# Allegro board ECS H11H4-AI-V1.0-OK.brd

Outline 200 x 210 mm; copper layers: TOP, PWR, GND, BOTTOM. Coordinates in mm from the lower left corner of the outline.
Outline path: 0,206.95 0,3.05 ; 0,206.95 arc(0.89,209.11) 3.05,210 ; 0,206.95 0,3.05 ; 0,3.05 arc(0.89,0.89) 3.05,0 ; 3.05,210 196.95,210 ; 3.05,210 196.95,210 ; 196.95,210 arc(199.11,209.11) 200,206.95 ; 3.05,0 196.95,0 ; 3.05,0 196.95,0 ; 196.95,0 arc(199.11,0.89) 200,3.05 ; 200,206.95 200,3.05 ; 200,206.95 200,3.05

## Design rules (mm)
net group DIFFPAIR351: nets CPU_BCLK_N CPU_BCLK_P
net group DIFFPAIR353: nets CPU_24MCLK_N CPU_24MCLK_P
net group DIFFPAIR381: nets USB_H1 USB_L1
net group DIFFPAIR382: nets USB_H2 USB_L2
net group DIFFPAIR422: nets USB+7 USB-7
net group DIFFPAIR436: nets VCORE_GSENS VCORE_SENS
net group DIFFPAIR439: nets VCORE_GT_GSENS VCORE_GT_SENS
net group DIFFPAIR448: nets USB3_TX_N2_C USB3_TX_P2_C
net group DIFFPAIR455: nets MXDIN_0 MXDIP_0
net group DIFFPAIR456: nets MXDIN_1 MXDIP_1
net group DIFFPAIR457: nets MXDIN_2 MXDIP_2
net group DIFFPAIR458: nets MXDIN_3 MXDIP_3
net group DIFFPAIR459: nets HSIN HSIP
net group DIFFPAIR460: nets GLAN_TX_N7 GLAN_TX_P7
net group DIFFPAIR461: nets HSON HSOP
net group DIFFPAIR462: nets GLAN_RX_N7 GLAN_RX_P7
net group DIFFPAIR463: nets DP_TX_N1 DP_TX_P1
net group DIFFPAIR464: nets DP_TX_N0 DP_TX_P0
net group DIFFPAIR465: nets DP_AUX_N DP_AUX_P
net group DIFFPAIR467: nets SATA3T_N0 SATA3T_P0
net group DIFFPAIR468: nets SATA3R_N0 SATA3R_P0
net group DIFFPAIR469: nets SATA3R_N1 SATA3R_P1
net group DIFFPAIR470: nets SATA3_TX_N1 SATA3_TX_P1
net group DIFFPAIR471: nets SATA3T_N1 SATA3T_P1
net group DIFFPAIR472: nets M_DQS_A_N8 M_DQS_A_P8
net group DIFFPAIR485: nets HDMI_CLK_N3 HDMI_CLK_P3
net group DIFFPAIR486: nets DDI3_TX_N3 DDI3_TX_P3
net group DIFFPAIR487: nets DDI3_TX_N2 DDI3_TX_P2
net group DIFFPAIR488: nets HDMI_TX_N0 HDMI_TX_P0
net group DIFFPAIR489: nets HDMI_TX_N1 HDMI_TX_P1
net group DIFFPAIR490: nets DDI3_TX_N1 DDI3_TX_P1
net group DIFFPAIR491: nets HDMI_TX_N2 HDMI_TX_P2
net group DIFFPAIR492: nets DDI3_TX_N0 DDI3_TX_P0
net group DIFFPAIR496: nets M_DQS_B_N8 M_DQS_B_P8
net group DIFFPAIR497: nets VR_CSN2 VR_CSP2
net group DIFFPAIR498: nets VR_CSN1 VR_CSP1
net group DIFFPAIR499: nets VR_CSN3 VR_CSP3
net group DIFFPAIR500: nets VR_CSN1A VR_CSP1A
net group DIFFPAIR501: nets VR_CSN2A VR_CSP2A
net group GLAN: nets GLAN_CLKN GLAN_CLKP
net group PCH-CLK: nets PEX16_100M_N PEX16_100M_P
net group VRD: nets VRD_THERMDA VRD_THERMDC
net group DDI1: nets DDI1_AUX_N DDI1_AUX_P DDI1_TX_N0 DDI1_TX_N1 DDI1_TX_P0 DDI1_TX_P1
net group DDR_DQS_A: nets M_DQS_A_N0 M_DQS_A_N1 M_DQS_A_N2 M_DQS_A_N3 M_DQS_A_N4 M_DQS_A_N5 M_DQS_A_N6 M_DQS_A_N7 M_DQS_A_P0 M_DQS_A_P1 M_DQS_A_P2 M_DQS_A_P3 M_DQS_A_P4 M_DQS_A_P5 M_DQS_A_P6 M_DQS_A_P7
net group DDR_DQS_B: nets M_DQS_B_N0 M_DQS_B_N1 M_DQS_B_N2 M_DQS_B_N3 M_DQS_B_N4 M_DQS_B_N5 M_DQS_B_N6 M_DQS_B_N7 M_DQS_B_P0 M_DQS_B_P1 M_DQS_B_P2 M_DQS_B_P3 M_DQS_B_P4 M_DQS_B_P5 M_DQS_B_P6 M_DQS_B_P7
net group DDRCLK-A: nets M_CLK_A_N0 M_CLK_A_N1 M_CLK_A_P0 M_CLK_A_P1
net group DDRCLK-B: nets M_CLK_B_N0 M_CLK_B_N1 M_CLK_B_P0 M_CLK_B_P1
net group DDRCMD-A: nets M_ACT_A_L M_BA_A0 M_BA_A1 M_BG_A0 M_BG_A1 M_MA_A0 M_MA_A1 M_MA_A2 M_MA_A3 M_MA_A4 M_MA_A5 M_MA_A6 M_MA_A7 M_MA_A8 M_MA_A9 M_MA_A10 M_MA_A11 M_MA_A12 M_MA_A13 M_MA_A14 M_MA_A15 M_MA_A16 M_PARITY_A
net group DDRCMD-B: nets M_ACT_B_L M_BA_B0 M_BA_B1 M_BG_B0 M_BG_B1 M_MA_B0 M_MA_B1 M_MA_B2 M_MA_B3 M_MA_B4 M_MA_B5 M_MA_B6 M_MA_B7 M_MA_B8 M_MA_B9 M_MA_B10 M_MA_B11 M_MA_B12 M_MA_B13 M_MA_B14 M_MA_B15 M_MA_B16 M_PARITY_B
net group DDRCTRL-A: nets M_CKE_A0 M_CKE_A1 M_CS_A_L0 M_CS_A_L1 M_ODT_A0 M_ODT_A1
net group DDRCTRL-B: nets M_CKE_B0 M_CKE_B1 M_CS_B_L0 M_CS_B_L1 M_ODT_B0 M_ODT_B1
net group DIFF-CLK: nets CPU_PCIBCLK_N
net group DIFFPAIR352: nets CPU_PCIBCLK_P
net group DMI: nets DMI_RX_N0 DMI_RX_N1 DMI_RX_N2 DMI_RX_N3 DMI_RX_P0 DMI_RX_P1 DMI_RX_P2 DMI_RX_P3 DMI_TX_N0 DMI_TX_N1 DMI_TX_N2 DMI_TX_N3 DMI_TX_P0 DMI_TX_P1 DMI_TX_P2 DMI_TX_P3
net group HDMI: nets HDMI_CLK_N3_R HDMI_CLK_P3_R HDMI_TX_N0_R HDMI_TX_N1_R HDMI_TX_N2_R HDMI_TX_P0_R HDMI_TX_P1_R HDMI_TX_P2_R
net group M_DATA_A: nets M_DATA_A0 M_DATA_A1 M_DATA_A2 M_DATA_A3 M_DATA_A4 M_DATA_A5 M_DATA_A6 M_DATA_A7 M_DATA_A8 M_DATA_A9 M_DATA_A10 M_DATA_A11 M_DATA_A12 M_DATA_A13 M_DATA_A14 M_DATA_A15 M_DATA_A16 M_DATA_A17 M_DATA_A18 M_DATA_A19 M_DATA_A20 M_DATA_A21 M_DATA_A22 M_DATA_A23 M_DATA_A24 M_DATA_A25 M_DATA_A26 M_DATA_A27 M_DATA_A28 M_DATA_A29 M_DATA_A30 M_DATA_A31 M_DATA_A32 M_DATA_A33 M_DATA_A34 M_DATA_A35 M_DATA_A36 M_DATA_A37 M_DATA_A38 M_DATA_A39 M_DATA_A40 M_DATA_A41 M_DATA_A42 M_DATA_A43 M_DATA_A44 M_DATA_A45 M_DATA_A46 M_DATA_A47 M_DATA_A48 M_DATA_A49 M_DATA_A50 M_DATA_A51 M_DATA_A52 M_DATA_A53 M_DATA_A54 M_DATA_A55 M_DATA_A56 M_DATA_A57 M_DATA_A58 M_DATA_A59 M_DATA_A60 M_DATA_A61 M_DATA_A62 M_DATA_A63 M_DATA_A_CB0 M_DATA_A_CB1 M_DATA_A_CB2 M_DATA_A_CB3 M_DATA_A_CB4 M_DATA_A_CB5 M_DATA_A_CB6 M_DATA_A_CB7
net group M_DATA_B: nets M_DATA_B0 M_DATA_B1 M_DATA_B2 M_DATA_B3 M_DATA_B4 M_DATA_B5 M_DATA_B6 M_DATA_B7 M_DATA_B8 M_DATA_B9 M_DATA_B10 M_DATA_B11 M_DATA_B12 M_DATA_B13 M_DATA_B14 M_DATA_B15 M_DATA_B16 M_DATA_B17 M_DATA_B18 M_DATA_B19 M_DATA_B20 M_DATA_B21 M_DATA_B22 M_DATA_B23 M_DATA_B24 M_DATA_B25 M_DATA_B26 M_DATA_B27 M_DATA_B28 M_DATA_B29 M_DATA_B30 M_DATA_B31 M_DATA_B32 M_DATA_B33 M_DATA_B34 M_DATA_B35 M_DATA_B36 M_DATA_B37 M_DATA_B38 M_DATA_B39 M_DATA_B40 M_DATA_B41 M_DATA_B42 M_DATA_B43 M_DATA_B44 M_DATA_B45 M_DATA_B46 M_DATA_B47 M_DATA_B48 M_DATA_B49 M_DATA_B50 M_DATA_B51 M_DATA_B52 M_DATA_B53 M_DATA_B54 M_DATA_B55 M_DATA_B56 M_DATA_B57 M_DATA_B58 M_DATA_B59 M_DATA_B60 M_DATA_B61 M_DATA_B62 M_DATA_B63 M_DATA_B_CB0 M_DATA_B_CB1 M_DATA_B_CB2 M_DATA_B_CB3 M_DATA_B_CB4 M_DATA_B_CB5 M_DATA_B_CB6 M_DATA_B_CB7
net group PCIE-16X: nets PEG_RX_N0 PEG_RX_N1 PEG_RX_N2 PEG_RX_N3 PEG_RX_N4 PEG_RX_N5 PEG_RX_N6 PEG_RX_N7 PEG_RX_N8 PEG_RX_N9 PEG_RX_N10 PEG_RX_N11 PEG_RX_N12 PEG_RX_N13 PEG_RX_N14 PEG_RX_N15 PEG_RX_P0 PEG_RX_P1 PEG_RX_P2 PEG_RX_P3 PEG_RX_P4 PEG_RX_P5 PEG_RX_P6 PEG_RX_P7 PEG_RX_P8 PEG_RX_P9 PEG_RX_P10 PEG_RX_P11 PEG_RX_P12 PEG_RX_P13 PEG_RX_P14 PEG_RX_P15 PEG_TX_C_N0 PEG_TX_C_N1 PEG_TX_C_N2 PEG_TX_C_N3 PEG_TX_C_N4 PEG_TX_C_N5 PEG_TX_C_N6 PEG_TX_C_N7 PEG_TX_C_N8 PEG_TX_C_N9 PEG_TX_C_N10 PEG_TX_C_N11 PEG_TX_C_N12 PEG_TX_C_N13 PEG_TX_C_N14 PEG_TX_C_N15 PEG_TX_C_P0 PEG_TX_C_P1 PEG_TX_C_P2 PEG_TX_C_P3 PEG_TX_C_P4 PEG_TX_C_P5 PEG_TX_C_P6 PEG_TX_C_P7 PEG_TX_C_P8 PEG_TX_C_P9 PEG_TX_C_P10 PEG_TX_C_P11 PEG_TX_C_P12 PEG_TX_C_P13 PEG_TX_C_P14 PEG_TX_C_P15 PEG_TX_N0 PEG_TX_N1 PEG_TX_N2 PEG_TX_N3 PEG_TX_N4 PEG_TX_N5 PEG_TX_N6 PEG_TX_N7 PEG_TX_N8 PEG_TX_N9 PEG_TX_N10 PEG_TX_N11 PEG_TX_N12 PEG_TX_N13 PEG_TX_N14 PEG_TX_N15 PEG_TX_P0 PEG_TX_P1 PEG_TX_P2 PEG_TX_P3 PEG_TX_P4 PEG_TX_P5 PEG_TX_P6 PEG_TX_P7 PEG_TX_P8 PEG_TX_P9 PEG_TX_P10 PEG_TX_P11 PEG_TX_P12 PEG_TX_P13 PEG_TX_P14 PEG_TX_P15
net group RGB: nets VGA_BLUE VGA_GREEN VGA_RED
net group SATA30: nets SATA3_RX_N0 SATA3_RX_N1 SATA3_RX_P0 SATA3_RX_P1 SATA3_TX_N0 SATA3_TX_P0
net group USB20: nets SMBDATA_STBY USB+5 USB+6 USB+8 USB-5 USB-6 USB-8 USB_N1 USB_N2 USB_N5 USB_N6 USB_N7 USB_N8 USB_P1 USB_P2 USB_P5 USB_P6 USB_P7 USB_P8
net group USB30: nets USB3_RX_N1 USB3_RX_N1_R USB3_RX_N2 USB3_RX_N2_R USB3_RX_N3 USB3_RX_N3_R USB3_RX_N4 USB3_RX_N4_R USB3_RX_P1 USB3_RX_P1_R USB3_RX_P2 USB3_RX_P2_R USB3_RX_P3 USB3_RX_P3_R USB3_RX_P4 USB3_RX_P4_R USB3_TX_N1 USB3_TX_N1_C USB3_TX_N1_R USB3_TX_N2 USB3_TX_N2_R USB3_TX_N3 USB3_TX_N3_C USB3_TX_N3_R USB3_TX_N4 USB3_TX_N4_C USB3_TX_N4_R USB3_TX_P1 USB3_TX_P1_C USB3_TX_P1_R USB3_TX_P2 USB3_TX_P2_R USB3_TX_P3 USB3_TX_P3_C USB3_TX_P3_R USB3_TX_P4 USB3_TX_P4_C USB3_TX_P4_R USB_N3 USB_N3_R USB_N4 USB_N4_R USB_P3 USB_P3_R USB_P4 USB_P4_R

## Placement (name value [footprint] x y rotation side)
ATX_12V  -  [ATX_PWR_4P_2]  190.73 163.65 180 top
ATX_POWER  -  [ATX_PWR_12P-RUIYE_2]  82.73 8.58 0 top
AUDIO  -  [AUDIO_JACK_13P-COLAY_2]  52.09 201.42 0 top
BAT1  +  [BATTERY_HOLDER_CR2032-LOTES]  35.22 131.27 180 top
BIOS_WP  -  [J3X1]  44.23 64.14 0 top
BZ  +  [BUZZER_1]  182.28 68.33 270 top
C1  -  [C0402_2]  179.24 204.16 180 top
C2  -  [C0402_2]  179.24 202.95 180 top
C3  -  [C0402_2]  166.15 202.57 270 top
C4  -  [C0402_2]  167.23 202.57 270 top
C5  -  [C0402_2]  103.1 202.44 0 top
C6  -  [C0402_2]  179.24 201.62 180 top
C7  -  [C0402_2]  179.24 200.28 180 top
C8  -  [C0402_2]  110.48 200.07 270 top
C9  -  [C0805_2]  112.7 199.76 180 top
C10  -  [C0603_2]  128.6 199.34 270 top
C11  -  [C0805_2]  103.16 199.14 270 top
C12  -  [C0402_2]  127.39 198.96 90 top
C13  -  [C0402_2]  179.24 198.95 180 top
C14  -  [C0402_2]  8.74 198.82 90 top
C15  -  [C0402_2]  134.02 197.55 0 top
C16  -  [C0402_2]  103.1 196.92 0 top
C17  -  [C0402_2]  118.21 196.86 270 top
C18  -  [C0402_2]  119.55 196.86 270 top
C19  -  [C0402_2]  121.13 196.86 270 top
C20  -  [C0402_2]  122.21 196.86 270 top
C21  -  [C0402_2]  123.29 196.86 270 top
C22  -  [C0402_2]  124.37 196.86 270 top
C23  -  [C0402_2]  125.45 196.86 270 top
C24  -  [C0402_2]  115.1 196.79 270 top
C25  -  [C0402_2]  116.62 196.79 270 top
C26  -  [C0402_2]  8.74 196.67 90 top
C27  -  [C0402_2]  134.02 196.47 0 top
C28  -  [C0402_2]  103.1 195.84 0 top
C29  -  [C0402_2]  134.02 195.4 0 top
C30  -  [C0402_2]  8.74 194.57 270 top
C31  -  [C0402_2]  134.02 194.32 0 top
C32  -  [C0402_2]  18.58 193.87 90 top
C33  -  [C0805_2]  17.06 193.81 90 top
C34  -  [C0805_2]  21.25 193.81 90 top
C35  -  [C0805_2]  23.22 193.81 90 top
C36  -  [C0805_2]  25.18 193.81 270 top
C37  -  [C0805_2]  27.15 193.81 270 top
C38  -  [C0402_2]  115.42 193.68 0 top
C39  -  [C0402_2]  117.83 193.68 0 top
C40  -  [C0402_2]  120.24 193.68 0 top
C41  -  [C0402_2]  134.02 193.24 0 top
C42  -  [C0402_2]  8.74 192.35 270 top
C43  -  [C0402_2]  134.02 192.16 0 top
C44  -  [C0402_2]  84.62 191.14 270 top
C45  -  [C0402_2]  134.02 191.08 0 top
C46  -  [C0402_2]  22.33 190.89 180 top
C47  -  [C0402_2]  104.5 190.89 90 top
C48  -  [C0402_2]  105.58 190.89 90 top
C49  -  [C0402_2]  107.16 190.89 90 top
C50  -  [C0402_2]  108.24 190.89 90 top
C51  -  [C0402_2]  109.39 190.89 90 top
C52  -  [C0402_2]  110.66 190.89 90 top
C53  -  [C0402_2]  111.8 190.89 90 top
C54  -  [C0402_2]  98.34 190.82 90 top
C55  -  [C0402_2]  41.5 190.57 180 top
C56  -  [C0402_2]  134.02 190 0 top
C57  -  [C0402_2]  141.45 189.62 0 top
C58  -  [C0805_2]  11.28 189.43 180 top
C59  -  [C0402_2]  138.15 189.11 270 top
C60  -  [C0805_2]  26.77 188.6 180 top
C61  -  [C0402_2]  11.66 187.89 180 top
C62  -  [C0402_2]  165.58 187.52 90 top
C63  -  [C0402_2]  166.85 187.52 90 top
C64  -  [C0402_2]  174.54 187.52 90 top
C65  -  [C0402_2]  163.55 187.14 0 top
C66  -  [C0402_2]  138.15 187.01 90 top
C67  -  [C0603_2]  11.28 186.7 0 top
C68  -  [C0805_2]  26.77 186.63 180 top
C69  -  [C0402_2]  58.84 186.56 270 top
C70  -  [C0402_2]  50.36 186.53 270 top
C71  -  [C0402_2]  54.37 186.53 270 top
C72  -  [C0402_2]  45.89 186.51 270 top
C73  -  [C0402_2]  41.19 186.19 180 top
C74  -  [C0402_2]  83.67 185.36 0 top
C75  -  [C0402_2]  138.15 184.85 90 top
C76  -  [C0805_2]  26.77 184.66 0 top
C77  -  [C0402_2]  93.89 184.31 90 top
C78  -  [C0402_2]  92.8 184.29 90 top
C79  -  [C0402_2]  94.97 184.28 90 top
C80  -  [C0402_2]  96.05 184.28 90 top
C81  -  [C0402_2]  163.55 183.71 0 top
C82  -  [C0603_2]  11.28 183.46 0 top
C83  -  [C0402_2]  127.48 183.01 180 top
C84  -  [C0402_2]  176.7 182.82 180 top
C85  -  [C0805_2]  26.77 182.7 0 top
C86  -  [C0402_2]  163.55 182.32 180 top
C87  -  [C0402_2]  161.27 182.19 0 top
C88  -  [C0402_2]  58.01 182.06 180 top
C89  -  [C0402_2]  91.03 181.93 90 top
C90  -  [C0402_2]  64.68 181.62 0 top
C91  -  [C0402_2]  77.13 181.55 0 top
C92  -  [C0402_2]  176.7 181.49 180 top
C93  -  [C0402_2]  158.85 181.36 0 top
C94  -  [C0402_2]  72.01 181.19 270 top
C95  -  [C0402_2]  63.09 181.11 270 top
C96  -  [C0402_2]  67.39 181.11 270 top
C97  -  [C0402_2]  79.79 181.04 270 top
C98  -  [C0402_2]  161.27 180.92 0 top
C99  -  [C0402_2]  10.39 180.85 0 top
C100  -  [C0402_2]  179.55 180.79 180 top
C101  -  [C0402_2]  179.55 179.71 180 top
C102  -  [C0603_2]  64.3 179.65 270 top
C103  -  [C0402_2]  161.27 179.14 180 top
C104  -  [C0402_2]  65.51 179.01 270 top
C105  -  [C0402_2]  14.9 178.82 180 top
C106  -  [C0402_2]  176.63 178.19 180 top
C107  -  [C0402_2]  161.27 178 180 top
C108  -  [C0402_2]  181.14 177.55 270 top
C109  -  [C0402_2]  179.55 177.04 180 top
C110  -  [C0805_2]  46.77 176.92 0 top
C111  -  [C0402_2]  163.55 176.85 0 top
C112  -  [C0402_2]  21.31 176.54 270 top
C113  -  [C0402_2]  22.45 176.54 270 top
C114  -  [C0402_2]  19.15 176.47 270 top
C115  -  [C0805_2]  16.55 176.35 270 top
C116  -  [C0402_2]  163.55 175.71 180 top
C117  -  [C0402_2]  89.89 175.33 0 top
C118  -  [C0402_2]  94.84 175.33 180 top
C119  -  [C0603_2]  46.77 175.27 0 top
C120  -  [C0402_2]  107.54 175.01 90 top
C121  -  [C0402_2]  50.33 174.57 270 top
C122  -  [C0402_2]  46.77 174 180 top
C123  -  [C0402_2]  162.66 173.81 90 top
C124  -  [C0402_2]  163.81 173.81 90 top
C125  -  [C0402_2]  168.38 173.81 90 top
C126  -  [C0402_2]  172.19 173.81 270 top
C127  -  [C0402_2]  174.47 173.81 270 top
C128  -  [C0402_2]  175.62 173.81 90 top
C129  -  [C0402_2]  176.76 173.81 90 top
C130  -  [C0402_2]  177.97 173.81 90 top
C131  -  [C0603_2]  169.9 173.55 90 top
C132  -  [C0805_2]  15.66 173.17 0 top
C133  -  [C0805_2]  123.17 172.92 270 top
C134  -  [C0805_2]  142.47 172.6 270 top
C135  -  [C0402_2]  126.53 172.28 270 top
C136  -  [C0603_4D7UF]  49.95 171.96 90 top
C137  -  [C0402_2]  146.91 171.96 270 top
C138  -  [C0805_2]  34.71 171.71 0 top
C139  -  [C0402_2]  106.59 170.19 180 top
C140  -  [C0402_2]  135.42 169.74 270 top
C141  -  [C0805_2]  11.02 169.61 0 top
C142  -  [C0402_2]  17.25 169.61 180 top
C143  -  [C0402_2]  166.09 169.17 270 top
C144  -  [C0402_2]  103.73 169.11 0 top
C145  -  [C0402_2]  106.59 169.11 180 top
C146  -  [C0402_2]  57 168.47 90 top
C147  -  [C0402_2]  58.08 168.47 90 top
C148  -  [C0402_2]  60.3 168.47 90 top
C149  -  [C0402_2]  184.57 168.47 0 top
C150  -  [C0402_2]  10.39 168.09 0 top
C151  -  [C0402_2]  110.72 167.84 270 top
C152  -  [C0402_2]  63.86 167.26 180 top
C153  -  [C0402_2]  116.37 167.14 90 top
C154  -  [C0402_2]  98.91 167.07 0 top
C155  -  [C0603_4D7UF]  53.7 166.95 0 top
C156  -  [C0402_2]  135.67 166.76 90 top
C157  -  [C0402_2]  109 165.87 90 top
C158  -  [C0402_2]  22.64 165.8 90 top
C159  -  [C0402_2]  54.27 165.68 0 top
C160  -  [C0402_2]  69.95 165.17 0 top
C161  -  [C0402_2]  73.89 165.17 180 top
C162  -  [C0402_2]  33.57 163.39 180 top
C163  -  [C0402_2]  33.57 165.55 180 top
C164  -  [C0603_4D7UF]  35.92 159.96 0 top
C165  -  [C0402_2]  63.86 164.6 0 top
C166  -  [C0603_2]  120.24 164.53 0 top
C167  -  [C0603_2]  138.79 164.53 0 top
C168  -  [C0402_2]  35.85 157.61 0 top
C169  -  [C0402_2]  54.24 163.53 180 top
C170  -  [C0402_2]  22.64 162.5 270 top
C171  -  [C0402_2]  54.24 162.45 180 top
C173  -  [C0402_2]  40.62 166.88 270 top
C174  -  [C0402_2]  97.83 162.18 270 top
C175  -  [C0805_2]  106.72 161.49 90 top
C176  -  [C0805_2]  108.69 161.49 90 top
C177  -  [C0805_2]  110.66 161.49 90 top
C178  -  [C0402_2]  62.65 160.91 0 top
C179  -  [C0402_2]  105.19 160.85 90 top
C181  -  [C0402_2]  65.13 159.71 0 top
C182  -  [C0402_2]  54.65 159.33 270 top
C183  -  [C0402_2]  55.73 159.33 270 top
C184  -  [C0402_2]  56.87 159.33 270 top
C185  -  [C0402_2]  59.03 159.33 270 top
C186  -  [C0805_2]  33.38 158.44 90 top
C187  -  [C0805_2]  25.82 158.57 90 top
C188  -  [C0805_2]  27.72 158.57 90 top
C189  -  [C0805_2]  29.63 158.57 90 top
C190  -  [C0402_2]  37.44 164.6 90 top
C191  -  [C0402_2]  22.14 158.5 90 top
C192  -  [C0402_2]  23.22 158.5 90 top
C193  -  [C0402_2]  24.3 158.5 270 top
C194  -  [C0402_2]  79.29 158.44 180 top
C195  -  [C0603_4D7UF]  62.71 157.74 180 top
C196  -  [C0402_2]  186.73 157.23 180 top
C197  -  [C0805_2]  42.9 159.45 90 top
C198  -  [C0402_2]  44.17 164.09 180 top
C199  -  [C0402_2]  133.39 156.22 90 top
C200  -  [C0402_2]  115.29 155.71 90 top
C201  -  [C0402_2]  11.66 155.07 270 top
C202  -  [C0402_2]  177.14 154.63 0 top
C203  -  [C0402_2]  74.08 153.68 180 top
C204  -  [C0805_2]  112.12 153.29 0 top
C205  -  [C0805_2]  44.17 162.12 180 top
C206  -  [C0402_2]  9.88 152.28 270 top
C207  -  [C0805_2]  112.12 150.75 0 top
C208  -  [C0402_2]  193.52 148.34 180 top
C209  -  [C0805_2]  106.72 148.09 270 top
C210  -  [C0805_2]  109.51 148.09 270 top
C211  -  [C0402_2]  111.35 148.09 90 top
C212  -  [C0402_2]  23.09 147.96 180 top
C213  -  [C0402_2]  23.09 146.88 180 top
C214  -  [C0402_2]  9.88 145.61 270 top
C215  -  [C0603_4D7UF]  112.94 144.6 180 top
C216  -  [C0402_2]  22.77 144.21 180 top
C217  -  [C0805_2]  194.22 143.83 180 top
C218  -  [C0402_2]  22.77 143.13 180 top
C219  -  [C0603_4D7UF]  114.91 142.5 180 top
C220  -  [C0402_2]  79.29 141.86 270 top
C221  -  [C0402_2]  22.64 140.91 180 top
C222  -  [C0805_2]  122.66 140.79 180 top
C223  -  [C0805_2]  130.28 140.79 0 top
C224  -  [C0805_2]  137.96 140.79 0 top
C225  -  [C0603_4D7UF]  126.47 140.72 180 top
C226  -  [C0603_4D7UF]  134.09 140.72 0 top
C227  -  [C0603_4D7UF]  143.04 140.72 0 top
C228  -  [C0603_2]  184.95 140.02 180 top
C229  -  [C0402_2]  22.64 139.83 180 top
C230  -  [C0402_2]  79.29 139.77 90 top
C231  -  [C0402_2]  189.97 138.82 270 top
C232  -  [C0402_2]  75.98 138.37 270 top
C233  -  [C0402_2]  164.19 137.67 0 top
C234  -  [C0402_2]  22.71 137.1 180 top
C235  -  [C0402_2]  80.87 136.59 90 top
C236  -  [C0402_2]  176.89 136.15 0 top
C237  -  [C0402_2]  22.71 136.02 180 top
C238  -  [C0402_2]  166.85 135.51 0 top
C239  -  [C0402_2]  72.24 135.07 0 top
C240  -  [C0402_2]  10.45 133.99 180 top
C241  -  [C0402_2]  85.57 133.8 90 top
C242  -  [C0402_2]  22.64 133.1 180 top
C243  -  [C0402_2]  72.3 132.78 180 top
C244  -  [C0402_2]  82.5 132.26 0 top
C245  -  [C0402_2]  22.64 132.02 180 top
C246  -  [C0402_2]  193.52 131.2 180 top
C247  -  [C0402_2]  22.64 130.94 180 top
C248  -  [C0402_2]  22.64 129.86 180 top
C249  -  [C0805_2]  83.29 129.48 90 top
C250  -  [C0805_2]  85.26 129.48 90 top
C251  -  [C0402_2]  86.84 129.48 90 top
C252  -  [C0805_2]  81.32 129.42 90 top
C253  -  [C0805_2]  161.96 128.72 90 top
C254  -  [C0402_2]  22.64 126.94 180 top
C255  -  [C0805_2]  194.22 126.69 180 top
C256  -  [C0402_2]  22.64 125.86 180 top
C257  -  [C0805_2]  161.96 125.35 90 top
C258  -  [C0402_2]  22.71 123.7 225 top
C259  -  [C0402_2]  23.47 122.94 225 top
C260  -  [C0603_2]  185.08 122.88 180 top
C261  -  [C0805_2]  161.96 121.99 270 top
C262  -  [C0402_2]  189.97 121.61 270 top
C263  -  [C0402_2]  23.41 120.59 225 top
C264  -  [C0805_2]  73.76 120.34 180 top
C265  -  [C0603_2]  10.52 120.21 270 top
C266  -  [C0402_2]  24.17 119.83 225 top
C267  -  [C0805_2]  77.13 119.83 0 top
C268  -  [C0805_2]  161.96 118.62 90 top
C269  -  [C0805_2]  119.67 118.56 180 top
C270  -  [C0805_2]  123.29 118.56 0 top
C271  -  [C0805_2]  127.61 118.56 0 top
C272  -  [C0805_2]  131.36 118.56 180 top
C273  -  [C0805_2]  73.76 118.37 180 top
C274  -  [C0805_2]  77.13 117.86 0 top
C275  -  [C0402_2]  10.71 117.16 0 top
C276  -  [C0402_2]  74.14 116.85 0 top
C277  -  [C0603_4D7UF]  115.8 116.78 0 top
C278  -  [C0805_2]  119.67 116.59 180 top
C279  -  [C0805_2]  123.29 116.59 0 top
C280  -  [C0805_2]  127.61 116.59 0 top
C281  -  [C0805_2]  131.36 116.59 180 top
C282  -  [C0402_2]  22.33 116.36 270 top
C283  -  [C0402_2]  23.41 116.36 270 top
C284  -  [C0603_4D7UF]  115.8 115.45 0 top
C285  -  [C0805_2]  161.96 115.26 270 top
C286  -  [C0603_4D7UF]  62.18 115.13 180 top
C287  -  [C0805_2]  119.67 114.62 180 top
C288  -  [C0805_2]  123.29 114.62 0 top
C289  -  [C0805_2]  127.61 114.62 0 top
C290  -  [C0805_2]  131.36 114.62 180 top
C291  -  [C0805_2]  41.39 114.42 0 top
C292  -  [C0402_2]  39.03 114.31 270 top
C293  -  [C0603_4D7UF]  115.8 114.12 0 top
C294  -  [C0402_2]  68.81 113.99 270 top
C295  -  [C0805_2]  70.33 113.99 270 top
C296  -  [C0402_2]  62.61 113.53 0 top
C297  -  [C0603_4D7UF]  115.8 112.78 0 top
C298  -  [C0805_2]  119.67 112.67 180 top
C299  -  [C0805_2]  123.29 112.67 0 top
C300  -  [C0805_2]  127.61 112.65 0 top
C301  -  [C0805_2]  131.36 112.65 180 top
C302  -  [C0805_2]  41.39 112.49 0 top
C303  -  [C0402_2]  60.49 112.38 180 top
C304  -  [C0402_2]  22.14 112.18 270 top
C305  -  [C0402_2]  23.15 112.18 270 top
C306  -  [C0402_2]  68.2 111.78 0 top
C307  -  [C0402_2]  70.28 111.78 0 top
C308  -  [C0402_2]  66.12 111.52 180 top
C309  -  [C0402_2]  64.21 111.42 270 top
C310  -  [C0402_2]  50.62 111.4 90 top
C311  -  [C0805_2]  115.99 111.13 0 top
C312  -  [C0805_2]  119.67 110.69 180 top
C313  -  [C0805_2]  123.29 110.69 0 top
C314  -  [C0805_2]  127.61 110.69 0 top
C315  -  [C0805_2]  131.36 110.69 180 top
C316  -  [C0402_2]  40.93 109.86 90 top
C317  -  [C0603_4D7UF]  116.18 109.48 0 top
C318  -  [C0805_2]  119.67 108.72 180 top
C319  -  [C0805_2]  123.29 108.72 0 top
C320  -  [C0805_2]  127.61 108.72 0 top
C321  -  [C0805_2]  131.36 108.72 180 top
C322  -  [C0805_2]  194.92 108.34 90 top
C323  -  [C0805_2]  60.3 108.21 180 top
C324  -  [C0402_2]  52.05 106.37 90 top
C325  -  [C0805_2]  60.3 106.24 180 top
C326  -  [C0402_2]  194.48 105.03 90 top
C327  -  [C0402_2]  8.99 104.78 180 top
C328  -  [C0402_2]  66.02 103.89 270 top
C329  -  [C0402_2]  10.58 101.54 270 top
C330  -  [C0402_2]  11.66 101.54 270 top
C331  -  [C0402_2]  66.02 101.22 90 top
C332  -  [C0402_2]  4.86 99.76 90 top
C333  -  [C0402_2]  30.65 100.21 180 top
C334  -  [C0402_2]  178.54 99.95 180 top
C335  -  [C0402_2]  30.65 99.13 180 top
C336  -  [C0402_2]  190.79 98.94 270 top
C337  -  [C0603_2]  185.08 98.88 180 top
C338  -  [C0402_2]  10.58 97.41 270 top
C339  -  [C0402_2]  11.66 97.41 270 top
C340  -  [C0603_2]  32.49 97.16 90 top
C341  -  [C0402_2]  182.35 94.68 270 top
C342  -  [C0603_2]  32.49 94.3 90 top
C343  -  [C0402_2]  10.58 93.22 270 top
C344  -  [C0402_2]  11.66 93.22 270 top
C345  -  [C0402_2]  6.2 91.98 180 top
C346  -  [C0402_2]  10.58 89.29 270 top
C347  -  [C0402_2]  11.66 89.29 270 top
C348  -  [C0805_2]  6.29 88.64 90 top
C349  -  [C0805_2]  8.25 88.64 90 top
C350  -  [C0402_2]  10.58 85.73 270 top
C351  -  [C0402_2]  11.66 85.73 270 top
C352  -  [C0402_2]  29.38 85.71 180 top
C353  -  [C0402_2]  22.14 85.03 270 top
C354  -  [C0402_2]  23.22 85.03 270 top
C355  -  [C0402_2]  24.49 85.03 270 top
C356  -  [C0402_2]  32.87 81.92 270 top
C357  -  [C0402_2]  7.91 78.36 180 top
C358  -  [C0402_2]  26.33 78.17 180 top
C359  -  [C0402_2]  32.23 78.05 0 top
C360  -  [C0402_2]  22.64 77.03 180 top
C361  -  [C0402_2]  187.68 76.9 180 top
C362  -  [C0805_2]  7.28 76.84 0 top
C363  -  [C0402_2]  26.33 76.65 180 top
C364  -  [C0603_2]  26.71 74.68 270 top
C365  -  [C0805_2]  110.4 68.01 180 top
C366  -  [C0805_2]  66.08 73.86 180 top
C367  -  [C0402_2]  32.23 73.48 180 top
C368  -  [C0805_2]  131.48 72.78 0 top
C369  -  [C0402_2]  56.11 72.52 0 top
C370  -  [C0402_2]  32.23 72.4 180 top
C371  -  [C0402_2]  42.9 72.08 270 top
C372  -  [C0805_2]  110.4 66.05 180 top
C373  -  [C0402_2]  46.36 72.05 270 top
C374  -  [C0402_2]  53.95 72.01 270 top
C375  -  [C0805_2]  35.92 72.08 180 top
C376  -  [C0805_2]  66.08 71.89 180 top
C377  -  [C0402_2]  56.11 71.44 0 top
C378  -  [C0805_2]  131.48 70.81 0 top
C379  -  [C0805_2]  35.92 70.11 180 top
C380  -  [C0805_2]  55.47 69.92 0 top
C381  -  [C0402_2]  38.2 69.16 270 top
C382  -  [C0805_2]  55.47 67.95 0 top
C383  -  [C0805_2]  55.47 65.98 180 top
C384  -  [C0402_2]  181.78 60.65 0 top
C385  -  [C0402_2]  192.82 60.97 180 top
C386  -  [C0402_2]  26.71 59.51 0 top
C387  -  [C0402_2]  187.17 59 180 top
C388  -  [C0402_2]  29.25 58.87 180 top
C389  -  [C0402_2]  10.33 58.43 0 top
C390  -  [C0402_2]  19.22 58.43 180 top
C391  -  [C0402_2]  42.96 58.24 0 top
C392  -  [C0402_2]  189.27 57.92 180 top
C393  -  [C0805_2]  22.33 57.35 270 top
C394  -  [C0603_2]  181.78 57.22 180 top
C395  -  [C0603_2]  184.63 57.22 180 top
C396  -  [C0402_2]  42.46 56.65 90 top
C397  -  [C0603_4D7UF]  181.78 55.89 180 top
C398  -  [C0603_4D7UF]  184.63 55.89 180 top
C399  -  [C0402_2]  29.25 55.82 180 top
C400  -  [C0402_2]  187.17 55.76 180 top
C401  -  [C0402_2]  57.63 55.7 270 top
C402  -  [C0603_4D7UF]  114.21 54.82 90 top
C403  -  [C0402_2]  181.78 54.68 180 top
C404  -  [C0402_2]  184.63 54.68 180 top
C405  -  [C0402_2]  115.48 54.62 90 top
C406  -  [C0603_4D7UF]  24.8 54.36 0 top
C407  -  [C0805_2]  28.61 54.3 180 top
C408  -  [C0402_2]  56.17 54.11 90 top
C409  -  [C0402_2]  117.77 54.11 90 top
C410  -  [C0402_2]  123.1 54.11 90 top
C411  -  [C0402_2]  127.61 54.11 90 top
C412  -  [C0402_2]  129.07 54.11 90 top
C413  -  [C0402_2]  181.78 53.6 180 top
C414  -  [C0402_2]  184.63 53.6 180 top
C415  -  [C0402_2]  189.27 53.6 180 top
C416  -  [C0402_2]  9.69 47.12 90 top
C417  -  [C0402_2]  23.6 46.42 180 top
C418  -  [C0402_2]  105.89 44.2 0 top
C419  -  [C0402_2]  113.7 44.2 180 top
C420  -  [C0603_4D7UF]  116.24 44.2 0 top
C421  -  [C0402_2]  118.78 44.2 0 top
C422  -  [C0402_2]  124.5 44.2 0 top
C423  -  [C0805_2]  49.25 44.14 180 top
C424  -  [C0402_2]  51.98 44.14 0 top
C425  -  [C0402_2]  54.08 44.14 0 top
C426  -  [C0402_2]  56.3 44.14 180 top
C427  -  [C0603_2]  58.78 44.14 180 top
C428  -  [C0402_2]  62.78 44.14 180 top
C429  -  [C0402_2]  71.67 44.14 180 top
C430  -  [C0402_2]  81 44.14 180 top
C431  -  [C0402_2]  90.27 44.14 180 top
C432  -  [C0402_2]  96.3 44.14 180 top
C433  -  [C0402_2]  102.4 44.14 180 top
C434  -  [C0402_2]  128.69 44.14 180 top
C435  -  [C0402_2]  135.99 44.14 180 top
C436  -  [C0402_2]  146.98 44.14 0 top
C437  -  [C0402_2]  155.61 44.14 0 top
C438  -  [C0402_2]  164.25 44.14 180 top
C439  -  [C0402_2]  9.69 43.95 270 top
C440  -  [C0603_2]  23.6 42.36 180 top
C441  -  [C0805_2]  31.47 36.14 180 top
C442  -  [C0805_2]  40.42 36.2 0 top
C443  -  [C0402_2]  36.17 35.95 180 top
C444  -  [C0402_2]  54.39 34.68 0 top
C445  -  [C0603_2]  58.4 34.55 180 top
C446  -  [C0603_2]  121.01 34.55 180 top
C447  -  [C0603_4D7UF]  114.53 34.49 0 top
C448  -  [C0603_4D7UF]  117.51 34.49 0 top
C449  -  [C0805_2]  42.58 34.23 0 top
C450  -  [C0805_2]  51.66 34.23 180 top
C451  -  [C0805_2]  188.7 34.23 180 top
C452  -  [C0402_2]  56.43 34.17 270 top
C453  -  [C0402_2]  127.93 34.11 270 top
C454  -  [C0603_2]  186.03 33.79 270 top
C455  -  [C0402_2]  54.39 33.6 0 top
C456  -  [C0402_2]  104.18 33.47 0 top
C457  -  [C0402_2]  160.5 33.47 180 top
C458  -  [C0805_2]  30.07 33.03 270 top
C459  -  [C0805_2]  94.59 32.9 90 top
C460  -  [C0805_2]  96.56 32.9 90 top
C461  -  [C0402_2]  189.33 32.71 0 top
C462  -  [C0402_2]  42.39 32.52 180 top
C463  -  [C0402_2]  47.98 32.45 270 top
C464  -  [C0603_4D7UF]  114.53 32.45 0 top
C465  -  [C0402_2]  127.36 32.33 180 top
C466  -  [C0402_2]  150.85 32.2 270 top
C467  -  [C0402_2]  133.96 31.82 270 top
C468  -  [C0402_2]  69.32 31.76 0 top
C469  -  [C0402_2]  73.95 31.69 180 top
C470  -  [C0402_2]  189.33 31.63 0 top
C471  -  [C0402_2]  167.11 30.74 180 top
C472  -  [C0402_2]  69.32 30.68 0 top
C473  -  [C0402_2]  73.95 30.61 180 top
C474  -  [C0402_2]  189.33 30.55 0 top
C475  -  [C0603_4D7UF]  114.53 30.42 0 top
C476  -  [C0805_2]  106.97 30.36 0 top
C477  -  [C0402_2]  94.65 29.66 0 top
C478  -  [C0402_2]  69.32 29.6 0 top
C479  -  [C0402_2]  73.95 29.53 180 top
C480  -  [C0402_2]  149.14 29.53 90 top
C481  -  [C0402_2]  189.33 29.47 0 top
C482  -  [C0402_2]  135.55 29.34 0 top
C483  -  [C0402_2]  69.32 28.52 0 top
C484  -  [C0402_2]  73.95 28.45 180 top
C485  -  [C0402_2]  189.33 28.39 0 top
C486  -  [C0402_2]  105.83 28.33 90 top
C487  -  [C0402_2]  135.55 28.2 180 top
C488  -  [C0402_2]  167.11 28.14 180 top
C489  -  [C0402_2]  189.33 27.31 0 top
C490  -  [C0402_2]  50.52 27.18 0 top
C491  -  [C0402_2]  12.29 27.06 0 top
C492  -  [C0402_2]  138.34 27.06 0 top
C493  -  [C0402_2]  19.22 26.74 180 top
C494  -  [C0402_2]  160 26.68 270 top
C495  -  [C0402_2]  50.52 26.1 180 top
C496  -  [C0402_2]  135.55 25.91 180 top
C497  -  [C0603_2]  189.01 25.85 180 top
C498  -  [C0402_2]  19.22 25.66 180 top
C499  -  [C0402_2]  41.95 25.15 180 top
C500  -  [C0402_2]  19.22 24.58 180 top
C501  -  [C0402_2]  127.29 24.58 180 top
C502  -  [C0402_2]  49.95 24.52 90 top
C503  -  [C0603_4D7UF]  132.18 24.39 180 top
C504  -  [C0402_2]  192.32 24.14 270 top
C505  -  [C0402_2]  193.4 24.14 90 top
C506  -  [C0402_2]  189.4 24.07 0 top
C507  -  [C0402_2]  167.11 23.82 180 top
C508  -  [C0402_2]  44.43 23.18 270 top
C509  -  [C0402_2]  19.22 23.5 180 top
C510  -  [C0805_2]  42.9 22.55 90 top
C511  -  [C0402_2]  167.11 22.74 180 top
C512  -  [C0603_4D7UF]  124.69 22.36 90 top
C513  -  [C0603_4D7UF]  126.02 22.36 90 top
C514  -  [C0603_4D7UF]  127.36 22.36 90 top
C515  -  [C0402_2]  93.7 21.91 90 top
C516  -  [C0402_2]  150.03 21.91 90 top
C517  -  [C0402_2]  151.11 21.91 90 top
C518  -  [C0402_2]  152.18 21.91 90 top
C519  -  [C0402_2]  153.26 21.91 90 top
C520  -  [C0402_2]  154.34 21.91 90 top
C521  -  [C0402_2]  155.42 21.91 90 top
C522  -  [C0402_2]  156.5 21.91 90 top
C523  -  [C0402_2]  157.58 21.91 90 top
C524  -  [C0402_2]  128.56 21.47 270 top
C525  -  [C0402_2]  131.61 21.34 90 top
C526  -  [C0402_2]  122.28 21.28 180 top
C527  -  [C0402_2]  28.55 21.15 0 top
C528  -  [C0402_2]  189.33 21.09 0 top
C529  -  [C0603_2]  144.82 20.83 270 top
C530  -  [C0805_2]  105.58 20.33 180 top
C531  -  [C0402_2]  110.02 20.26 90 top
C532  -  [C0402_2]  29.82 19.88 0 top
C533  -  [C0402_2]  125.13 19.88 90 top
C534  -  [C0402_2]  189.27 19.82 180 top
C535  -  [C0402_2]  93.96 19.69 0 top
C536  -  [C0402_2]  31.41 22.8 90 top
C537  -  [C0402_2]  32.49 22.8 270 top
C538  -  [C0402_2]  167.11 19.25 180 top
C539  -  [C0402_2]  131.04 19.18 180 top
C540  -  [C0402_2]  133.71 18.67 90 top
C541  -  [C0805_2]  90.78 17.85 180 top
C542  -  [C0402_2]  167.11 17.09 180 top
C543  -  [C0603_2]  189.33 16.39 0 top
C544  -  [C0805_2]  90.78 15.88 180 top
C545  -  [C0402_2]  187.24 15.69 270 top
C546  -  [C0402_2]  25.63 12.77 270 top
C547  -  [C0805_2]  49.7 15.25 90 top
C548  -  [C0805_2]  52.05 15.25 90 top
C549  -  [C0805_2]  54.39 15.25 90 top
C550  -  [C0402_2]  27.66 16.07 180 top
C551  -  [C0603_2]  168.31 15.12 90 top
C552  -  [C0402_2]  75.03 14.36 180 top
C553  -  [C0402_2]  79.86 14.36 0 top
C554  -  [C0402_2]  81.95 14.36 180 top
C555  -  [C0402_2]  89.26 14.36 180 top
C556  -  [C0402_2]  91.42 14.36 0 top
C557  -  [C0402_2]  185.65 14.1 0 top
C558  -  [C0402_2]  170.98 13.59 270 top
C559  -  [C0402_2]  172.06 13.59 270 top
C560  -  [C0402_2]  176 13.59 270 top
C561  -  [C0402_2]  180.25 13.59 270 top
C562  -  [C0402_2]  182.16 13.59 90 top
C563  -  [C0402_2]  183.24 13.59 90 top
C564  -  [C0402_2]  193.21 13.47 90 top
C565  -  [C0402_2]  195.36 13.47 270 top
C566  -  [C0402_2]  131.1 12.9 0 top
C567  -  [C0805_2]  185.59 11.88 270 top
C568  -  [C0402_2]  175.43 11.12 270 top
C569  -  [C0603_2]  176.63 11.12 270 top
C570  -  [C0402_2]  139.99 10.86 90 top
C571  -  [C0402_2]  11.79 10.67 270 top
C572  -  [C0402_2]  167.11 10.67 0 top
C573  -  [C0402_2]  149.39 10.48 90 top
C574  -  [C0402_2]  23.98 9.78 0 top
C575  -  [C0402_2]  21.06 9.72 180 top
C576  -  [C0603_2]  111.29 8.64 270 top
C577  -  [C0402_2]  119.36 8.26 270 top
C578  -  [C0402_2]  121.9 8.26 270 top
C579  -  [C0402_2]  125.13 8.26 90 top
C580  -  [C0402_2]  129.32 8.26 270 top
C581  -  [C0402_2]  134.66 8.26 270 top
C582  -  [C0603_2]  105.39 7.88 0 top
C583  -  [C0402_2]  75.67 2.93 180 top
C584  -  [C0402_2]  81.06 2.93 0 top
C585  -  [C0603_2]  66.02 21.02 0 top
C586  -  [C0402_2]  58.59 6.48 0 top
C587  -  [C0402_2]  53.82 7.88 0 top
C588  -  [C0402_2]  27.22 9.21 90 top
C589  -  [C0402_2]  49.63 10.55 90 top
C590  -  [C0402_2]  49.63 5.09 90 top
C591  -  [C0402_2]  59.6 11.63 180 top
C592  -  [C0402_2]  63.03 11.75 0 top
C593  -  [C0805_2]  44.87 159.45 90 top
C594  -  [C0402_2]  14.33 36.26 90 top
C595  -  [C0402_2]  137.9 9.09 0 top
C596  -  [C0402_2]  18.52 33.22 0 top
C597  -  [C0402_2]  132.82 34.11 90 top
C598  -  [C0402_2]  62.33 9.47 180 top
C600  -  [C0402_2]  60.22 8.71 270 top
CHOKE1  -  [WCM2012F2S_1]  140.44 196.79 0 top
CHOKE2  -  [WCM2012F2S_1]  140.44 195.01 0 top
CHOKE3  -  [WCM2012F2S_1]  140.44 192.98 0 top
CHOKE4  -  [WCM2012F2S_1]  140.44 191.2 0 top
CHOKE5  -  [WCM2012F2S_1]  90.27 188.03 90 top
CHOKE6  -  [WCM2012F2S_1]  92.05 188.03 90 top
CHOKE7  -  [WCM2012F2S_1]  94.15 188.03 90 top
CHOKE8  -  [WCM2012F2S_1]  95.8 188.03 90 top
CHOKE9  -  [WCM2012F2S_1]  86.34 185.81 90 top
CHOKE10  -  [WCM2012F2S_1]  88.11 185.81 90 top
CHOKE11  -  [WCM2012F2S_1]  15.79 26.05 180 top
CHOKE12  -  [WCM2012F2S_1]  15.79 24.28 180 top
CHOKE13  -  [WCM2012F2S_1]  15.79 21.98 180 top
CHOKE14  -  [WCM2012F2S_1]  15.79 20.2 180 top
CLR_CMOS  -  [J3X1]  26.52 40.52 270 top
CMK1  -  [CMM21_1]  17.18 30.22 270 top
CMK2  -  [CMM21_1]  17.18 28.52 270 top
CN1  -  [8P4C]  151.8 9.85 0 top
CN2  -  [8P4C]  155.93 9.85 0 top
CN3  -  [8P4C]  160.06 9.85 0 top
CN4  -  [8P4C]  164.19 9.85 0 top
CODEC  -  [LQFP48]  18.71 184.66 90 top
COM  -  [J5X2_PANEL]  142.41 14.86 0 top
CPU  -  [LGA1151-INTEL]  123.37 113.73 0 top
CPU_FAN  -  [J4X1_WAFER]  192.32 81.67 270 top
D1  -  [SOT23_3L]  6.13 198.19 90 top
D2  -  [SOT23_2MM_2]  14.39 196.22 180 top
D3  -  [SOT23_3L]  6.2 192.98 270 top
D4  -  [SOT23_3L]  40.68 188.35 90 top
D5  -  [SOT23_3L]  56.6 185.59 180 top
D6  -  [SOT23_3L]  48.12 185.57 180 top
D7  -  [SOD_523]  76.49 178.5 90 top
D8  -  [SOD_523]  79.86 178.5 90 top
D9  -  [SOD_523]  62.97 178.25 90 top
D10  -  [SOD_523]  66.78 178.25 90 top
D11  -  [SOT23_3L]  13.82 176.22 0 top
D12  -  [SOT23_GDS_2]  42.46 175.27 0 top
D13  -  [SOD_523]  8.29 162.18 270 top
D14  -  [SOT23_2MM_2]  8.8 149.48 0 top
D15  -  [SOT23_3L]  10.52 107.32 180 top
D16  -  [BAT54_132_2]  188.32 89.92 0 top
D17  +  [SOD_123_2]  187.68 81.03 270 top
D18  +  [SOD_123_2]  194.92 58.87 270 top
D19  -  [SOT23_3L]  27.03 51.31 0 top
D20  -  [SOT23_2MM_2]  26.33 46.74 180 top
D21  +  [SOD_123_2]  158.41 31.12 90 top
D22  +  [SOD_123_2]  149.14 25.85 270 top
D23  +  [SOD_123_2]  158.41 25.6 90 top
D24  -  [SOT23_3L]  108.69 12.07 180 top
D25  -  [SOT23_3L]  112.12 12.07 180 top
D26  +  [SOD_123_2]  168.95 9.15 180 top
D27  +  [SOD_123_2]  51.66 6.55 90 top
DIMM1  -  [DDR4_288P_1]  179.19 41.87 270 top
DIMM2  -  [DDR4_288P_1]  179.19 51.76 270 top
EC1  +  [EC2_4_H5MM]  36.36 187.9 0 top
EC2  +  [EC2_4_H5MM]  31.6 187.84 0 top
EC3  +  [EC2D5_6D3_H11MM]  100.24 186.7 0 top
EC4  +  [EC2D5_6D3_H11MM]  31.92 180.85 0 top
EC5  +  [EC2D5_6D3_H11MM]  39.03 180.85 0 top
EC6  +  [EC2D5_6D3_H11MM]  85.76 180.35 0 top
EC7  +  [EC3D5_8_H11MM_1P]  131.74 174.38 0 top
EC8  +  [EC3D5_8_H11MM_1P]  27.79 164.98 270 top
EC9  +  [EC3D5_8_H11MM_1P]  191.68 153.49 270 top
EC11  +  [EC2D5_6D3_H8MM]  119.23 145.55 0 top
EC12  +  [EC2D5_6D3_H8MM]  126.34 145.55 0 top
EC13  +  [EC2D5_6D3_H8MM]  133.52 145.55 0 top
EC14  +  [EC2D5_6D3_H8MM]  140.69 145.55 0 top
EC15  +  [EC2D5_6D3_H8MM]  166.6 141.99 270 top
EC16  +  [EC2D5_6D3_H8MM]  166.68 131.51 270 top
EC17  +  [EC2D5_6D3_H8MM]  166.68 124.4 270 top
EC18  +  [EC2D5_6D3_H8MM]  166.68 117.29 270 top
EC19  +  [EC3D5_8_H11MM_1P]  191.75 114.31 270 top
EC20  +  [EC2D5_6D3_H8MM]  166.68 110.18 270 top
EC21  +  [EC2D5_6D3_H11MM]  192.51 69.86 270 top
EC22  +  [EC2D5_6D3_H11MM]  16.04 41.03 270 top
EC23  +  [EC2D5_6D3_H9MM]  38.08 21.15 0 top
EC24  +  [EC2D5_6D3_H9MM]  117.32 20.39 0 top
EC25  +  [EC3D5_8_H13MM_1P]  59.47 19.25 0 top
EC26  +  [EC3D5_8_H11MM_1P]  84.49 19.25 0 top
EC27  +  [EC2D5_6D3_H11MM]  16.04 15.31 270 top
EC28  +  [EC2D5_6D3_H8MM]  16.04 5.47 270 top
EC29  +  [EC2D5_6D3_H8MM]  23.91 5.47 270 top
EC30  +  [EC2D5_6D3_H8MM]  30.96 153.1 270 top
F1  -  [FUSE_SMD_1]  128.18 192.28 90 top
F_AUDIO  -  [J5X2_AUDIO_1]  6.71 183.2 270 top
F_PANEL  -  [J7X2_PANEL_10P]  106.46 4.58 0 top
F_USB  -  [J5X2_USB_1394]  6.52 41.73 270 top
FB1  -  [FB0402_2]  115.42 194.82 0 top
FB2  -  [FB0402_2]  117.83 194.82 0 top
FB3  -  [FB0402_2]  120.24 194.82 0 top
FB4  -  [FB0603_2]  60.55 158.95 270 top
FB5  -  [FB0805_2]  66.08 19.37 180 top
FB6  -  [FB0805_2]  66.08 17.4 180 top
FB7  -  [FB0805_2]  66.08 15.44 180 top
H1  -  [HOLE8_5]  36.17 199.84 0 top
H2  -  [HOLE8_5]  193.65 176.98 0 top
H3  -  [HOLE8_5]  36.17 44.9 0 top
H4  -  [HOLE8_5]  193.65 44.9 0 top
HDMI  -  [HDMI_19P-F_SMD-HIGH-TOP_5]  153.73 204.72 180 top
INT_SPK  -  [J4X2_4P]  6.71 169.61 270 top
L1  -  [FB0603_2]  176.76 202.95 0 top
L2  -  [FB0603_2]  176.76 201.62 0 top
L3  -  [FB0402_2]  103.1 201.36 0 top
L4  -  [FB0603_2]  176.76 200.28 0 top
L5  -  [FB0603_2]  176.76 198.95 0 top
L6  -  [FB0603_2]  41.25 191.84 0 top
L7  -  [FB0402_2]  103.42 190.89 90 top
L8  -  [FB0603_2]  44.68 186.19 90 top
L9  -  [FB0603_2]  60.03 186.17 90 top
L10  -  [FB0603_2]  51.55 186.15 90 top
L11  -  [FB0603_2]  53.18 186.15 90 top
L12  -  [FB0603_2]  40.87 184.98 0 top
L13  -  [WCM2012F2S_1]  54.39 180.66 180 top
L14  -  [WCM2012F2S_1]  54.39 178.89 180 top
L15  -  [CHOKE-APL0806P-R60M]  180.57 162.82 270 top
L16  -  [L0805_2]  6.39 162.38 90 top
L17  -  [CHOKE_R30_PT6D3X1D4MM_1]  128.25 155.71 90 top
L18  -  [CHOKE_R30_PT6D3X1D4MM_1]  145.01 155.71 90 top
L19  -  [CHOKE_1R0M_1]  105.51 154.88 0 top
L20  -  [CHOKE_3R3M_PT5MM_SMD]  38.01 153.74 180 top
L21  -  [CHOKE_R30_PT6D3X1D4MM_1]  176.95 141.86 0 top
L22  -  [CHOKE_PT6D2MM_SMD_2P]  76.3 125.74 270 top
L23  -  [CHOKE_R30_PT6D3X1D4MM_1]  176.95 123.39 0 top
L24  -  [CHOKE_R30_PT6D3X1D4MM_1]  176.95 113.48 0 top
L25  -  [FB0603_2]  192.38 34.23 0 top
L26  -  [WCM2012F2S_1]  10.2 34.17 270 top
L27  -  [WCM2012F2S_1]  11.85 34.17 270 top
L28  -  [CHOKE_1R0M_1]  35.98 30.1 180 top
L29  -  [CHOKE_1R0M_1]  121.13 28.83 180 top
L30  -  [FB0805_2]  122.21 22.8 180 top
L31  -  [FB0603_2]  194.48 22.42 180 top
L32  -  [CHOKE_2R2M_PT6D6X6D6MM]  34.65 7.88 270 top
LPT  -  [J13X2_LPT_1]  162.03 4.58 0 top
ME_DISABLE  -  [J3X1]  34.77 64.14 0 top
NOREF  -  []  126.19 63.92 0 top
NOREF#2  -  [unnamed#2]  194.12 187.83 0 top
NOREF#3  -  []  20.42 51.12 0 top
NOREF#4  -  [unnamed#2]  192.7 10.67 0 top
NOREF#5  -  []  60.17 139.39 270 top
NOREF#6  -  []  563.23 -711.1 90 top
NOREF#7  -  []  563.23 -711.1 90 top
NOREF#8  -  []  200 210 0 top
NOREF#9  -  []  23.98 -49.72 180 top
NOREF#10  -  []  563.23 -711.1 90 top
NOREF#11  -  []  -2.33 -4.39 90 top
NOREF#12  -  [unnamed#2]  194.92 5.08 0 top
NOREF#13  -  []  563.23 -711.1 90 top
NOREF#14  -  []  200 210 0 top
NOREF#15  -  []  133.02 -10.7 0 top
NOREF#16  -  []  200 210 270 top
NOREF#17  -  [unnamed#2]  10.77 6.99 0 top
NOREF#18  -  [unnamed#2]  5.08 5.08 0 top
NOREF#19  -  []  563.23 -711.1 90 top
NOREF#20  -  []  107.3 270.96 0 top
NOREF#21  -  []  247.82 296.87 0 top
NOREF#22  -  []  286.12 -58.22 90 top
NOREF#23  -  []  200 210 270 top
NOREF#24  -  []  -30.33 81.46 180 top
NOREF#25  -  []  225.78 276.8 0 top
NOREF#26  -  [unnamed#2]  5.84 204.21 0 top
NOREF#27  -  []  563.23 -711.1 90 top
NOREF#28  -  []  92.05 61.54 180 bottom
NOREF#29  -  []  110.34 60.39 180 bottom
NOREF#30  -  []  131.17 61.03 180 bottom
NOREF#31  -  []  100.56 60.52 180 bottom
NOREF#32  -  [unnamed#2]  10.77 6.99 180 bottom
NOREF#33  -  [unnamed#2]  192.7 10.67 180 bottom
NOREF#34  -  [unnamed#2]  5.84 204.21 180 bottom
NOREF#35  -  []  86.59 53.92 180 bottom
NOREF#36  -  []  139.17 60.78 180 bottom
NOREF#37  -  [unnamed#2]  194.12 187.83 180 bottom
NOREF#38  -  []  120.24 61.03 180 bottom
PCH1  -  [BGA837-INTEL_1]  48.78 89.18 90 top
PCIE16X  -  [PCIE_X16_164P_4]  17.43 152.91 0 top
PFB1  -  [FB0805_2]  168.82 204.16 90 top
PFB2  -  [FB0805_2]  110.66 164.98 90 top
PFB3  -  [FB0805_2]  42.14 164.92 90 top
PFB4  -  [FB0805_2]  87.1 133.04 90 top
PFB5  -  [FB0805_2]  32.66 20.77 180 top
PSKM  -  [KB_MS-MINI-DIN_1]  189.46 201.14 0 top
Q1  -  [SOT363_6P]  9.88 202.76 270 top
Q2  -  [SOT363_6P]  14.2 202.76 270 top
Q3  -  [SOT363_6P]  18.77 202.76 270 top
Q4  -  [SOT363_6P]  22.77 202.76 270 top
Q5  -  [SOT363_6P]  26.65 202.76 270 top
Q6  -  [SOT23_GDS_2]  140.31 200.09 180 top
Q7  -  [SOT363_6P]  18.77 198.44 270 top
Q8  -  [SOT23_GDS_2]  175.81 192.35 180 top
Q9  -  [SOT23_GDS_2]  128.05 186.7 0 top
Q10  -  [SOT23_GDS_2]  133.33 185.81 0 top
Q11  -  [SOT23_GDS_2]  133.33 181.87 0 top
Q12  -  [SOT23_GDS_2]  137.2 181.87 0 top
Q13  -  [SOT23_BCE_2]  35.22 175.71 0 top
Q14  -  [SOT23_GDS_2]  38.84 175.27 0 top
Q15  -  [SOT23_GDS_2]  52.81 173.87 270 top
Q16  -  [SOT23_BCE_2]  23.98 173.17 0 top
Q17  -  [SOT23_BCE_2]  27.6 173.17 0 top
Q18  -  [SOT23_BCE_2]  31.22 173.17 0 top
Q19  -  [SOT23_BCE_2]  11.28 172.41 270 top
Q20  -  [SOT23_BCE_2]  137.9 170.5 270 top
Q21  -  [SOT23_GDS_2]  7.53 144.79 180 top
Q22  -  [SOT23_GDS_2]  7.53 140.91 180 top
Q23  -  [SOT23_GDS_2]  7.53 137.04 0 top
Q24  -  [SOT23_GDS_2]  7.53 133.17 0 top
Q25  -  [SOT23_BCE_2]  7.66 129.29 270 top
Q26  -  [SOT23_BCE_2]  7.66 125.67 270 top
Q27  -  [SOT23_BCE_2]  7.66 122.05 270 top
Q28  -  [SOT23_BCE_2]  7.66 118.43 270 top
Q29  -  [SOT23_BCE_2]  6.26 114.69 180 top
Q30  -  [SOT23_GDS_2]  9.94 114.69 180 top
Q31  -  [SOT23_GDS_2]  6.15 107.35 0 top
Q32  -  [SOT23_GDS_2]  6.13 103.45 0 top
Q33  -  [SOT23_GDS_2]  188.32 93.8 180 top
Q34  -  [SOT23_GDS_2]  194.09 93.8 0 top
Q35  -  [SOT23_GDS_2]  50.33 63.51 270 top
Q36  -  [SOT23_BCE_2]  28.36 63.44 90 top
Q37  -  [SOT23_GDS_2]  48.43 59.7 270 top
Q38  -  [SOT23_GDS_2]  52.17 59.7 0 top
Q39  -  [SOT23_BCE_2]  13.31 57.16 270 top
Q40  -  [SOT23_GDS_2]  25.12 57.03 180 top
Q41  -  [SOT23_BCE_2]  192.13 55.7 0 top
Q42  -  [SOT23_BCE_2]  45.95 55 180 top
Q43  -  [SOT23_GDS_2]  49.63 55 0 top
Q44  -  [SOT23_GDS_2]  23.22 38.68 180 top
Q45  -  [SOT23_GDS_2]  27.03 32.45 180 top
Q46  -  [SOT23_GDS_2]  142.22 31.31 270 top
Q47  -  [SOT23_GDS_2]  146.09 31.31 270 top
Q48  -  [SOT23_BCE_2]  161.27 30.93 0 top
Q49  -  [SOT23_GDS_2]  29.06 28.58 180 top
Q50  -  [SOT23_GDS_2]  142.22 27.69 90 top
Q51  -  [SOT23_GDS_2]  146.09 27.69 90 top
Q52  -  [SOT23_GDS_2]  29.06 24.71 180 top
Q53  -  [SOT23_BCE_2]  136.18 20.45 90 top
Q54  -  [SOT23_BCE_2]  142.22 20.45 90 top
Q55  -  [SOT23_BCE_2]  193.97 19.94 90 top
Q56  -  [SOT23_GDS_2]  127.48 17.79 0 top
Q57  -  [SOT23_GDS_2]  26.92 18.61 180 top
Q58  -  [SOT23_GDS_2]  94.27 17.21 180 top
Q59  -  [SOT23_GDS_2]  97.96 17.21 180 top
Q60  -  [SOT23_GDS_2]  30.58 17.09 0 top
Q61  -  [SOT23_BCE_2]  193.97 16.33 270 top
Q62  -  [SOT23_BCE_2]  131.23 15.25 90 top
Q63  -  [SOT23_GDS_2]  188.7 12.58 180 top
Q64  -  [SOT23_BCE_2]  97.96 10.48 180 top
Q65  -  [SOT23_BCE_2]  101.58 10.48 180 top
Q66  -  [SOT23_BCE_2]  105.19 10.48 180 top
Q67  -  [SOT23_BCE_2]  115.61 10.48 0 top
Q68  -  [SOT23_BCE_2]  143.42 10.17 180 top
Q69  -  [SOT23_BCE_2]  147.04 10.17 0 top
Q84  -  [SOT363_PT065_MOSFET]  15.72 33.98 90 top
Q85  -  [SOT23_GDS_2]  34.39 16.27 270 top
Q86  -  [SOT363_PT065_MOSFET]  66.14 8.2 90 top
QCGH1  -  [Q_TDSON8-GDS-4]  188.7 128.72 270 top
QCGH2  -  [Q_TDSON8-GDS-4]  190.16 107 270 top
QCGL1  -  [Q_TDSON8-GDS-4]  173.39 131.58 180 top
QCGL2  -  [Q_TDSON8-GDS-4]  173.77 105.29 0 top
QCGL3  -  [Q_TDSON8-GDS-4]  181.9 131.58 180 top
QCGL4  -  [Q_TDSON8-GDS-4]  182.28 105.29 0 top
QCH1  -  [Q_TDSON8-GDS-4]  144.5 167.14 0 top
QCH2  -  [Q_TDSON8-GDS-4]  125.2 167.46 0 top
QCH3  -  [Q_TDSON8-GDS-4]  188.7 145.87 270 top
QCL1  -  [Q_TDSON8-GDS-4]  136.63 152.15 270 top
QCL2  -  [Q_TDSON8-GDS-4]  119.86 152.15 270 top
QCL3  -  [Q_TDSON8-GDS-4]  173.39 150.06 180 top
QCL4  -  [Q_TDSON8-GDS-4]  136.63 160.66 270 top
QCL5  -  [Q_TDSON8-GDS-4]  119.86 160.66 270 top
QCL6  -  [Q_TDSON8-GDS-4]  181.9 150.06 180 top
QD5H1  -  [Q_TDSON8-GDS-4]  45.7 16.45 0 top
QD5L1  -  [Q_TDSON8-GDS-4]  45.31 8.58 90 top
QN1  -  [SOT23_GDS_2]  184.7 93.8 180 top
QN2  -  [SOT23_2MM_2]  184.63 90.18 270 top
QN3  -  [SOT23_2MM_2]  142.47 24.2 90 top
QN4  -  [DFN6_PT065_SM2203NSQG]  122.72 18.55 270 top
QN5  -  [SOT23_BCE_2]  66.59 11.31 270 top
QN7  -  [SOT23_GDS_2]  58.9 3.88 270 top
R1  -  [R0402_2]  9.75 205.36 180 top
R2  -  [R0402_2]  11.85 205.36 0 top
R3  -  [R0402_2]  13.95 205.36 180 top
R4  -  [R0402_2]  16.04 205.36 180 top
R5  -  [R0402_2]  18.14 205.36 180 top
R6  -  [R0402_2]  20.23 205.36 0 top
R7  -  [R0402_2]  22.26 205.36 180 top
R8  -  [R0402_2]  24.36 205.36 0 top
R9  -  [R0402_2]  26.45 205.36 180 top
R10  -  [R0402_2]  28.55 205.36 0 top
R11  -  [R0402_2]  8.48 201.11 180 top
R12  -  [R0402_2]  10.58 201.11 0 top
R13  -  [R0402_2]  17.18 200.16 180 top
R14  -  [R0402_2]  19.34 200.16 0 top
R15  -  [R0402_2]  104.69 200.09 90 top
R16  -  [R0402_2]  106.34 200.09 90 top
R17  -  [R0402_2]  107.8 200.09 90 top
R18  -  [R0402_2]  13.44 199.01 90 top
R19  -  [R0402_2]  15.34 199.01 90 top
R20  -  [R0402_2]  9.82 198.82 270 top
R21  -  [R0402_2]  111.99 198.13 0 top
R22  -  [R0402_2]  111.99 197.05 0 top
R23  -  [R0805_2]  127.74 196.92 0 top
R24  -  [R0402_2]  9.82 196.67 270 top
R25  -  [R0402_2]  27.15 196.54 90 top
R26  -  [R0402_2]  25.18 196.47 90 top
R27  -  [R0402_2]  103.1 194.76 0 top
R28  -  [R0402_2]  112.12 194.63 0 top
R29  -  [R0402_2]  9.82 194.57 90 top
R30  -  [R0402_2]  122.15 194.38 90 top
R31  -  [R0402_2]  123.23 194.38 90 top
R32  -  [R0402_2]  124.37 194.38 90 top
R33  -  [R0402_2]  125.45 194.38 90 top
R34  -  [R0402_2]  19.72 193.87 90 top
R35  -  [R0402_2]  103.1 193.68 0 top
R36  -  [R0402_2]  112.12 193.55 180 top
R37  -  [R0402_2]  103.1 192.6 180 top
R38  -  [R0402_2]  12.17 192.54 270 top
R39  -  [R0402_2]  13.25 192.54 270 top
R40  -  [R0402_2]  14.39 192.54 90 top
R41  -  [R0402_2]  112.12 192.47 0 top
R42  -  [R0402_2]  9.82 192.35 90 top
R43  -  [R0402_2]  30.01 191.65 90 top
R44  -  [R0402_2]  31.09 191.65 90 top
R45  -  [R0402_2]  39.22 191.18 270 top
R46  -  [R0402_2]  97.26 190.82 90 top
R47  -  [R0402_2]  33.44 190.76 270 top
R48  -  [R0402_2]  34.52 190.76 270 top
R49  -  [R0402_2]  27.79 190.63 90 top
R50  -  [R0402_2]  28.93 190.63 90 top
R51  -  [R0402_2]  173.46 190.13 270 top
R52  -  [R0402_2]  165.39 189.94 90 top
R53  -  [R0402_2]  166.6 189.94 90 top
R54  -  [R0402_2]  168 189.94 270 top
R55  -  [R0402_2]  169.14 189.94 270 top
R56  -  [R0402_2]  175.11 189.62 0 top
R57  -  [R0402_2]  156.44 189.43 0 top
R58  -  [R0402_2]  160.95 189.43 0 top
R59  -  [R0402_2]  163.55 189.43 0 top
R60  -  [R0402_2]  137.07 189.11 90 top
R61  -  [R0603-SHORT_2]  83.8 189.05 0 top
R62  -  [R0402_2]  163.55 188.35 0 top
R63  -  [R0402_2]  156.44 188.28 180 top
R64  -  [R0402_2]  160.95 188.28 0 top
R65  -  [R0603-SHORT_2]  83.8 187.65 0 top
R66  -  [R0402_2]  171.3 187.52 270 top
R67  -  [R0402_2]  172.38 187.52 270 top
R68  -  [R0402_2]  173.46 187.52 270 top
R69  -  [R0402_2]  175.62 187.52 90 top
R70  -  [R0402_2]  176.7 187.52 270 top
R71  -  [R0402_2]  177.78 187.52 90 top
R72  -  [R0402_2]  137.07 187.01 270 top
R73  -  [R0402_2]  158.92 186.95 0 top
R74  -  [R0402_2]  161.01 186.95 0 top
R75  -  [R0402_2]  163.55 186 0 top
R76  -  [R0402_2]  161.01 185.87 180 top
R77  -  [R0402_2]  156.82 185.87 0 top
R78  -  [R0402_2]  158.92 185.87 0 top
R79  -  [R0402_2]  11.6 185.45 0 top
R80  -  [R0402_2]  176.7 185.43 0 top
R81  -  [R0402_2]  38.84 185.36 90 top
R82  -  [R0402_2]  179.87 185.17 180 top
R83  -  [R0402_2]  137.07 184.85 90 top
R84  -  [R0402_2]  163.55 184.79 0 top
R85  -  [R0402_2]  158.98 184.79 180 top
R86  -  [R0402_2]  178.28 184.66 270 top
R87  -  [R0402_2]  181.46 184.66 90 top
R88  -  [R0402_2]  34.84 184.47 90 top
R89  -  [R0402_2]  35.98 184.47 90 top
R90  -  [R0402_2]  83.67 184.22 0 top
R91  -  [R0402_2]  127.48 184.22 0 top
R92  -  [R0402_2]  161.96 184.22 270 top
R93  -  [R0402_2]  50.88 184.19 180 top
R94  -  [R0402_2]  53.86 184.19 0 top
R95  -  [R0402_2]  45.38 184.16 0 top
R96  -  [R0402_2]  59.37 184.16 180 top
R97  -  [R0402_2]  179.87 184.09 0 top
R98  -  [R0402_2]  176.7 183.9 180 top
R99  -  [R0402_2]  156.88 183.71 180 top
R100  -  [R0402_2]  158.98 183.71 180 top
R101  -  [R0402_2]  130.91 183.14 90 top
R102  -  [R0402_2]  181.46 182.5 90 top
R103  -  [R0402_2]  139.55 182.31 270 top
R104  -  [R0402_2]  89.95 181.93 270 top
R105  -  [R0603-SHORT_2-NMNP]  45.25 181.87 270 top
R106  -  [R0402_2]  181.65 180.79 0 top
R107  -  [R0402_2]  66.27 181.11 90 top
R108  -  [R0402_2]  78.72 181.04 90 top
R109  -  [R0402_2]  130.91 180.98 270 top
R110  -  [R0402_2]  163.55 180.92 180 top
R111  -  [R0402_2]  12.8 180.47 90 top
R112  -  [R0402_2]  176.63 180.41 0 top
R113  -  [R0402_2]  158.85 180.22 180 top
R114  -  [R0402_2]  25.63 179.9 270 top
R115  -  [R0402_2]  26.77 179.9 270 top
R116  -  [R0402_2]  27.92 179.9 270 top
R117  -  [R0402_2]  176.63 179.33 0 top
R118  -  [R0402_2]  158.85 179.14 0 top
R119  -  [R0402_2]  163.55 179.14 180 top
R120  -  [R0402_2]  77.64 178.95 90 top
R121  -  [R0402_2]  78.72 178.95 270 top
R122  -  [R0402_2]  11.79 178.89 0 top
R123  -  [R0402_2]  179.55 178.12 180 top
R124  -  [R0402_2]  158.85 178 180 top
R125  -  [R0402_2]  163.55 178 180 top
R126  -  [R0402_2]  43.28 177.74 0 top
R127  -  [R0402_2]  182.22 177.55 90 top
R128  -  [R0402_2]  176.63 177.04 180 top
R129  -  [R0402_2]  61.82 176.92 270 top
R130  -  [R0402_2]  64.11 176.92 270 top
R131  -  [R0402_2]  65.51 176.92 270 top
R132  -  [R0402_2]  158.85 176.92 180 top
R133  -  [R0402_2]  161.27 176.85 0 top
R134  -  [R0603-SHORT_2-NMNP]  25.5 176.66 270 top
R135  -  [R0402_2]  23.53 176.6 270 top
R136  -  [R0402_2]  18.07 176.54 270 top
R137  -  [R0402_2]  20.23 176.54 90 top
R138  -  [R0402_2]  52.17 176.28 0 top
R139  -  [R0402_2]  176.63 175.97 0 top
R140  -  [R0402_2]  159.11 175.71 0 top
R141  -  [R0402_2]  161.27 175.71 0 top
R142  -  [R0402_2]  10.01 175.27 90 top
R143  -  [R0402_2]  173.28 173.86 90 top
R144  -  [R0402_2]  160.19 173.81 270 top
R145  -  [R0402_2]  161.58 173.81 90 top
R146  -  [R0402_2]  164.95 173.81 270 top
R147  -  [R0402_2]  166.09 173.81 270 top
R148  -  [R0402_2]  167.23 173.81 270 top
R149  -  [R0402_2]  171.04 173.81 90 top
R150  -  [R0402_2]  179.05 173.81 90 top
R151  -  [R0402_2]  33.95 173.23 180 top
R152  -  [R0402_2]  36.04 173.23 180 top
R153  -  [R0402_2]  38.27 172.79 180 top
R154  -  [R0402_2]  19.41 172.09 180 top
R155  -  [R0402_2]  14.33 171.58 180 top
